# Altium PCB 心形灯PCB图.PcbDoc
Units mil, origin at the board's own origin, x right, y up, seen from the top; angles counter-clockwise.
Board outline 5315 x 3937.01 mil, 2 copper layers (Top Layer, Bottom Layer); 75 components, 69 nets, 202 pads, 0 vias.
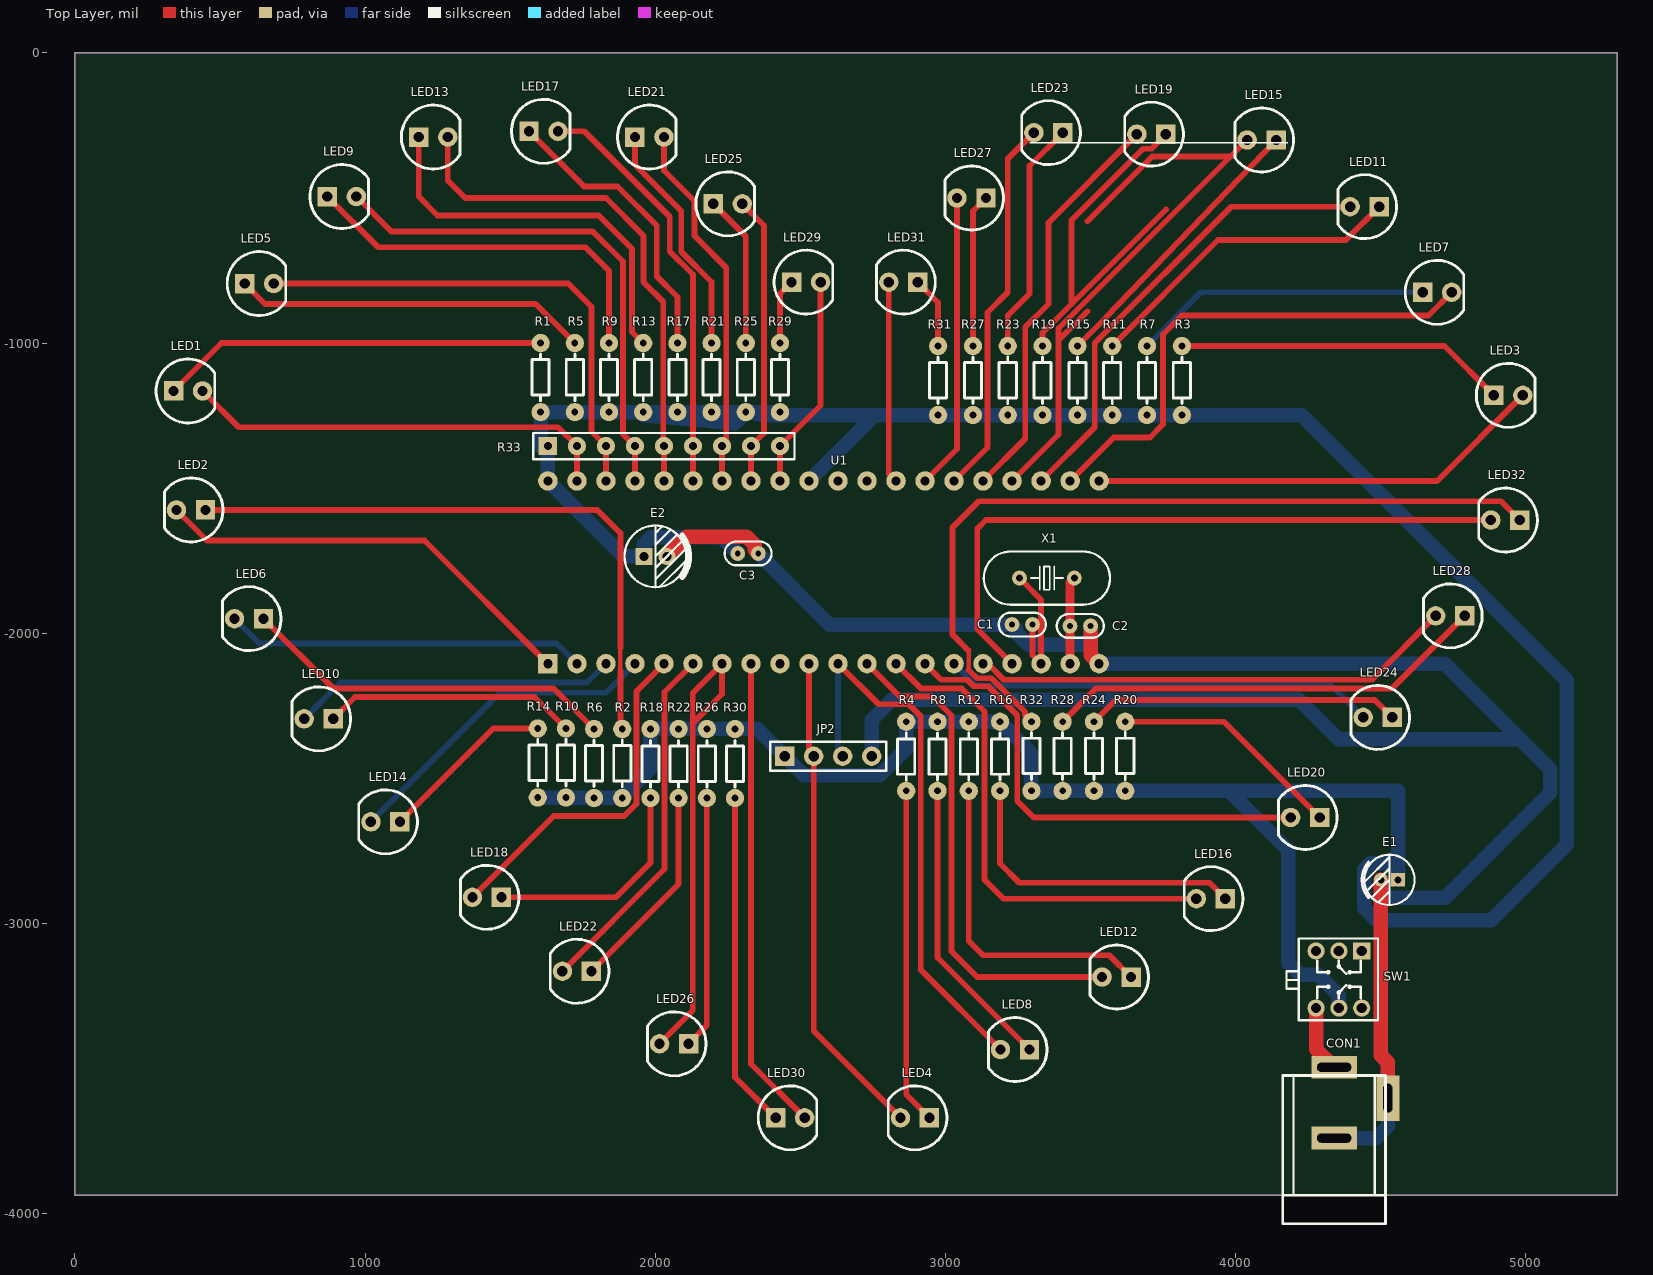
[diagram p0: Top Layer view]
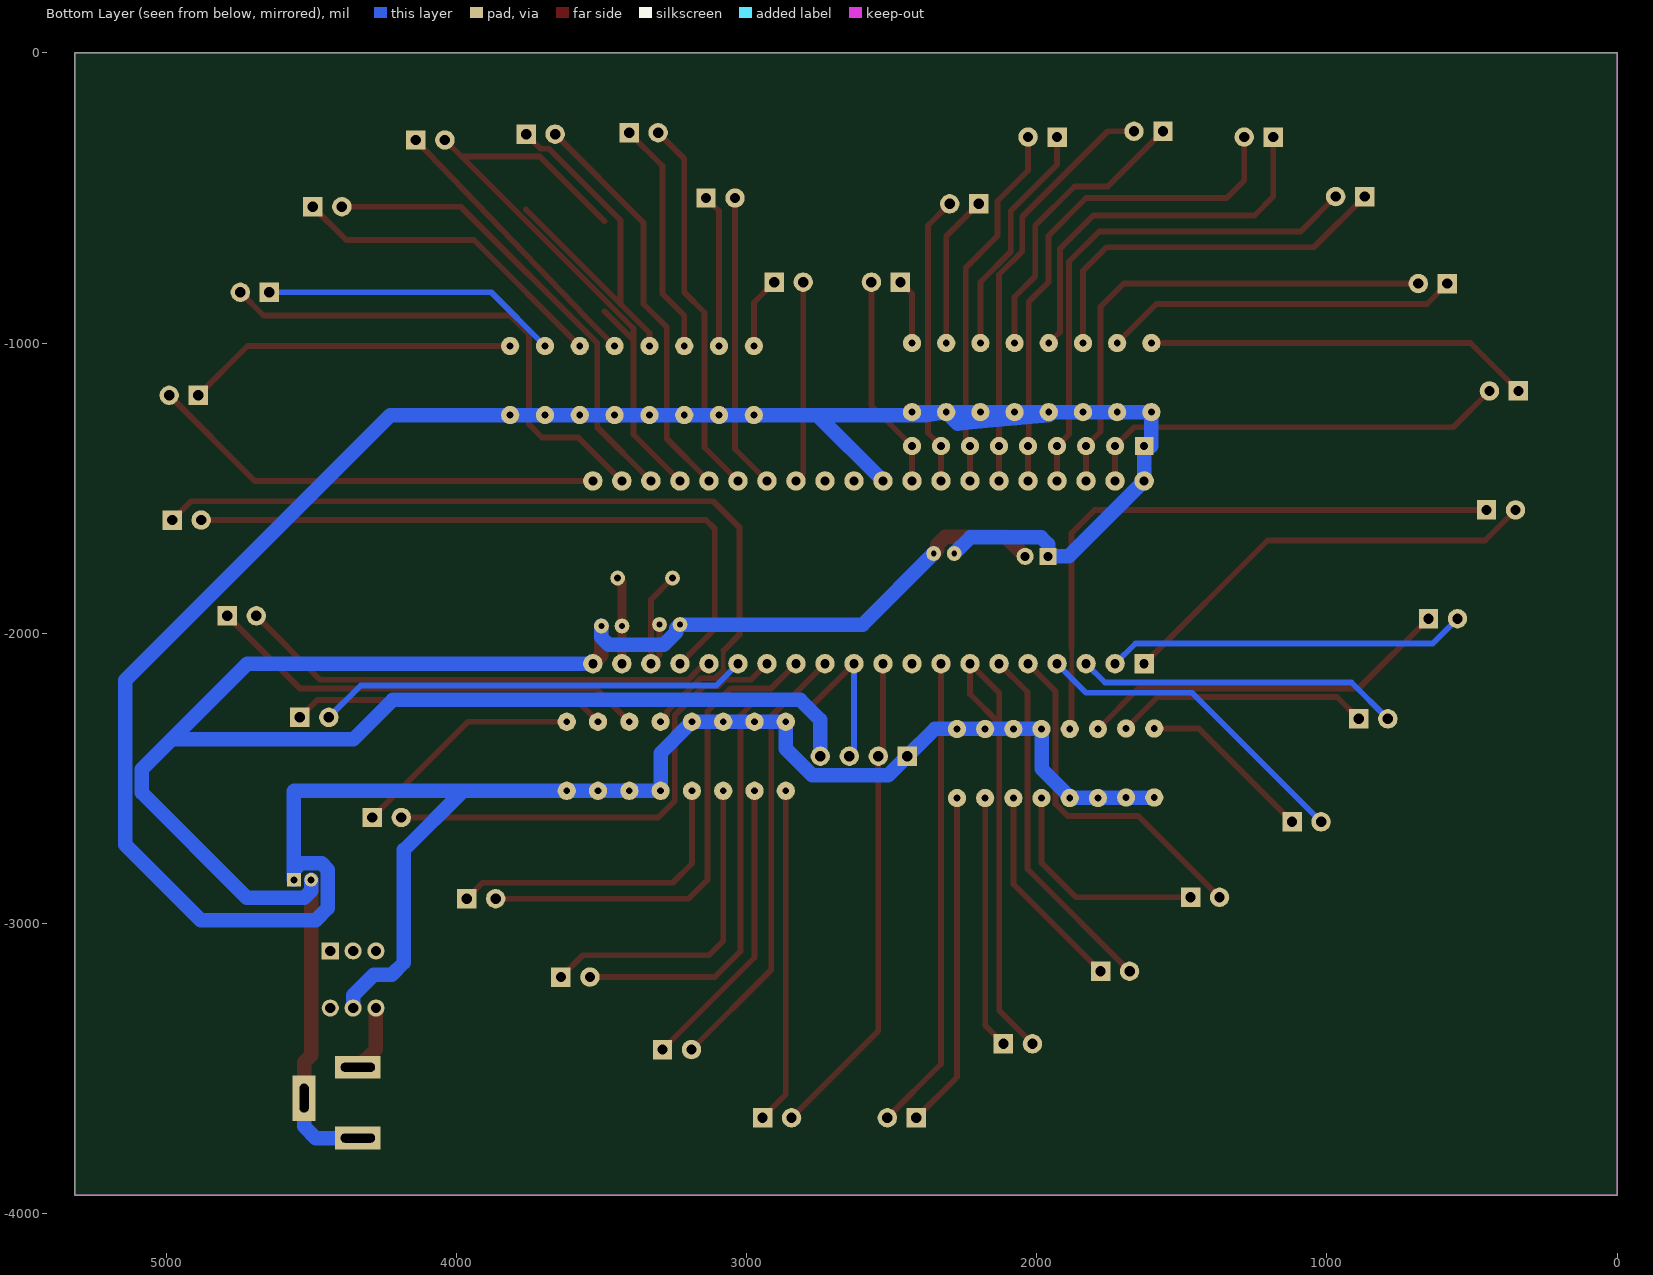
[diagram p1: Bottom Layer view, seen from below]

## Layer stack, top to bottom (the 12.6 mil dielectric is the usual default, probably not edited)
Top Solder: solder mask 0.4, Solder Resist, Dk 3.5
Top Layer: signal copper 1.4
Dielectric 1: dielectric 12.6, FR-4, Dk 4.8
Bottom Layer: signal copper 1.4
Bottom Solder: solder mask 0.4, Solder Resist, Dk 3.5

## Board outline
0,-3937.01 0,0 5315,0 5315,-3937.01

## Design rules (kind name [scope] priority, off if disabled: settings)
Clearance [All] p1: gap=7
PolygonConnect [All] p1: connectstyle=Relief reliefconductorwidth=10 reliefentries=4 polygonreliefangle="90 Angle" airgapwidth=10
RoutingVias [All] p1: holewidth=28 width=50 viastyle="Through Hole" minholewidth=28 minwidth=50 maxholewidth=28 maxwidth=50
SolderMaskExpansion [All] p1: expansion=4
Width Width-POWER [InNetClass('POWER')] p1: maxlimit=60 minlimit=50 preferedwidth=50
Width Width_1 [All] p2: maxlimit=30 minlimit=10 preferedwidth=20
30 further rules are at their usual default settings.

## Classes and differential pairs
net class POWER: +5V GND VCC

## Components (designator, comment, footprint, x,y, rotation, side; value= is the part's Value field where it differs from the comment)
C1 "104" "CC 1.8*3.6" 3265,-1970 r0 top
C2 "104" "CC 1.8*3.6" 3465,-1975 r180 top
C3 "104" "CC 1.8*3.6" 2320,-1725 r180 top
CON1 "3.5*1.3" DC-005 4340,-3740 r270 top
E1 "10uF/16V" "CAP 1.5*4*8" 4530.47,-2850 r180 top
E2 "100uF/16V" "CAP 2.0*5*11" 2000.63,-1735 r0 top
JP2 "TTL下载" HDR2.54-LI-4P 2596.06,-2423.94 r0 top
LED1 "红色" "LED 5MM-W" 390,-1165 r0 top
LED2 "红色" "LED 5MM-W" 400,-1575 r180 top
LED3 "红色" "LED 5MM-W" 4940,-1180 r0 top
LED4 "红色" "LED 5MM-W" 2895,-3670 r180 top
LED5 "红色" "LED 5MM-W" 635,-795 r0 top
LED6 "红色" "LED 5MM-W" 600,-1950 r180 top
LED7 "红色" "LED 5MM-W" 4695,-825 r0 top
LED8 "红色" "LED 5MM-W" 3240,-3435 r180 top
LED9 "红色" "LED 5MM-W" 920,-495 r0 top
LED10 "红色" "LED 5MM-W" 840,-2295 r180 top
LED11 "红色" "LED 5MM-W" 4445,-530 r180 top
LED12 "红色" "LED 5MM-W" 3590,-3185 r180 top
LED13 "红色" "LED 5MM-W" 1235,-290 r0 top
LED14 "红色" "LED 5MM-W" 1070,-2650 r180 top
LED15 "红色" "LED 5MM-W" 4090,-300 r180 top
LED16 "红色" "LED 5MM-W" 3915,-2915 r180 top
LED17 "红色" "LED 5MM-W" 1615,-270 r0 top
LED18 "红色" "LED 5MM-W" 1420,-2910 r180 top
LED19 "红色" "LED 5MM-W" 3710,-280 r180 top
LED20 "红色" "LED 5MM-W" 4240,-2635 r180 top
LED21 "红色" "LED 5MM-W" 1980,-290 r0 top
LED22 "红色" "LED 5MM-W" 1730,-3165 r180 top
LED23 "红色" "LED 5MM-W" 3355,-275 r180 top
LED24 "红色" "LED 5MM-W" 4490,-2290 r180 top
LED25 "红色" "LED 5MM-W" 2250,-520 r0 top
LED26 "红色" "LED 5MM-W" 2065,-3415 r180 top
LED27 "红色" "LED 5MM-W" 3090,-500 r180 top
LED28 "红色" "LED 5MM-W" 4740,-1940 r180 top
LED29 "红色" "LED 5MM-W" 2520,-790 r0 top
LED30 "红色" "LED 5MM-W" 2465,-3670 r0 top
LED31 "红色" "LED 5MM-W" 2855,-790 r180 top
LED32 "红色" "LED 5MM-W" 4930,-1610 r180 top
R1 "1K" "RS 1/8W" 1605,-1120 r270 top
R2 "1K" "RS 1/8W" 1886.43,-2450 r270 top
R3 "1K" "RS 1/8W" 3815,-1130 r270 top
R4 "1K" "RS 1/8W" 2865,-2423.11 r90 top
R5 "1K" "RS 1/8W" 1722.86,-1120 r270 top
R6 "1K" "RS 1/8W" 1789.29,-2450 r270 top
R7 "1K" "RS 1/8W" 3695,-1130 r270 top
R8 "1K" "RS 1/8W" 2972.86,-2423.11 r90 top
R9 "1K" "RS 1/8W" 1840.71,-1120 r270 top
R10 "1K" "RS 1/8W" 1692.14,-2448.11 r270 top
R11 "1K" "RS 1/8W" 3575,-1130 r270 top
R12 "1K" "RS 1/8W" 3080.71,-2423.11 r90 top
R13 "1K" "RS 1/8W" 1958.57,-1120 r270 top
R14 "1K" "RS 1/8W" 1595,-2448.11 r270 top
R15 "1K" "RS 1/8W" 3455,-1130 r270 top
R16 "1K" "RS 1/8W" 3188.57,-2423.11 r90 top
R17 "1K" "RS 1/8W" 2076.43,-1120 r270 top
R18 "1K" "RS 1/8W" 1983.57,-2448.11 r90 top
R19 "1K" "RS 1/8W" 3335,-1130 r270 top
R20 "1K" "RS 1/8W" 3620,-2425 r270 top
R21 "1K" "RS 1/8W" 2194.28,-1120 r270 top
R22 "1K" "RS 1/8W" 2080.71,-2448.11 r90 top
R23 "1K" "RS 1/8W" 3215,-1130 r270 top
R24 "1K" "RS 1/8W" 3512.14,-2425 r270 top
R25 "1K" "RS 1/8W" 2312.14,-1120 r270 top
R26 "1K" "RS 1/8W" 2177.86,-2448.11 r90 top
R27 "1K" "RS 1/8W" 3095,-1130 r270 top
R28 "1K" "RS 1/8W" 3404.29,-2425 r270 top
R29 "1K" "RS 1/8W" 2430,-1120 r270 top
R30 "1K" "RS 1/8W" 2275,-2448.11 r90 top
R31 "1K" "RS 1/8W" 2975,-1130 r270 top
R32 "1K" "RS 1/8W" 3296.43,-2425 r270 top
R33 "103" "R SIP9-2.54" 2030,-1355 r0 top
SW1 "KET 7X7" "KFT DIP-7X7" 4356.26,-3193.43 r180 top
U1 "STC89C52RC" 单片机40 1630,-2105 r90 top
X1 "12MHz" "OSC HC-49U" 3350,-1810 r180 top

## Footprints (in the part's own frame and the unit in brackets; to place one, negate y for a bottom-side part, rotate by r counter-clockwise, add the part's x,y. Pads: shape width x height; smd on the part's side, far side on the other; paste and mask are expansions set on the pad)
"CAP 1.5*4*8" [mm] "脚距1.5mm直径4mm高度8mm"
  rect 1.2x1.2 hole 0.6: 1(-0.75,0)
  round 1.2 hole 0.6: 2(0.75,0)
  silkscreen extent -2.2,-2.2 2.41,2.2, body extent -2,-2 2.02,2, height 8.04
"CAP 2.0*5*11" [mm] "脚距2mm直径5mm高度11mm"
  rect 1.5x1.5 hole 0.8: 1(-1,0)
  round 1.5 hole 0.8: 2(1,0)
  silkscreen extent -2.7,-2.7 2.96,2.7, body extent -2.5,-2.5 2.51,2.5, height 11.04
"CC 1.8*3.6" [mm] "脚距1.8mm直径3.6mm"
  round 1.3 hole 0.5: 1(-0.9,0) 2(0.9,0)
  silkscreen extent -2.05,-1.04 2.05,1.04, body extent -1.8,-0.8 1.8,0.8, height 3.6
DC-005 [mm] "5.5*2.1mm，DC30V,2.5A"
  rect 2x4 hole 0.8 slot 3 at 90 deg: 1(-6.2,0) 2(0,0)
  rect 4x2 hole 0.8 slot 2.5 at 0 deg: 3(-3.5,4.7)
  silkscreen extent -5.48,-4.5 7.5,4.5, body extent -6.55,-4.5 7.5,4.8, height 11.2
HDR2.54-LI-4P [mm] "排针，4脚"
  rect 1.7x1.7 hole 0.9: 1(-3.81,0)
  round 1.7 hole 0.9: 2(-1.27,0) 3(1.27,0) 4(3.81,0)
  silkscreen extent -5.08,-1.27 5.08,1.27, body extent -5.08,-1.27 5.08,1.27, height 8.5
"KFT DIP-7X7" [mm] "自锁开关，规格：7*7mm"
  rect 1.5x1.5 hole 0.9: 1(-2,-2.5)
  round 1.5 hole 0.9: 2(0,-2.5) 3(2,-2.5) 4(2,2.5) 5(0,2.5) 6(-2,2.5)
  silkscreen extent -3.42,-3.58 4.58,3.56, body extent -3.5,-3.5 3.5,3.5, height 11.2
"LED 5MM-W" [mm] "白色5mm直插LED"
  rect 1.7x1.7 hole 0.9: 1(-1.27,0)
  round 1.7 hole 0.9: 2(1.27,0)
  silkscreen extent -2.8,-2.8 2.33,2.8, body extent -2.85,-2.85 2.45,2.85, height 8.75
"OSC HC-49U" [mm]
  round 1.3 hole 0.6: 1(-2.4,0) 2(2.4,0)
  silkscreen extent -5.52,-2.32 5.52,2.33, body extent -5.53,-2.33 5.52,2.32, height 13.95
"R SIP9-2.54" [mm] "22.6mm*5mm*2.2mm(长*宽*厚)"
  rect 1.6x1.6 hole 0.7: 1(-10.16,0)
  round 1.6 hole 0.7: 2(-7.62,0) 3(-5.08,0) 4(-2.54,0) 5(0,0) 6(2.54,0) 7(5.08,0) 8(7.62,0) 9(10.16,0)
  silkscreen extent -11.43,-1.14 11.43,1.14, body extent -11.31,-0.96 11.31,0.96, height 5.2
"RS 1/8W" [mm] "直插色环电阻，脚距6mm，直径1.5mm"
  round 1.6 hole 0.6: 1(-3.048,0) 2(3,0)
  silkscreen extent -2.1,-0.75 2,0.75, body extent -3.22,-0.76 3.23,0.76, height 1.52
单片机40 [mm]
  rect 1.7x1.7 hole 0.8: 1(0,0)
  round 1.7 hole 0.8: 2(0,-2.54) 3(0,-5.08) 4(0,-7.62) 5(0,-10.16) 6(0,-12.7) 7(0,-15.24) 8(0,-17.78) 9(0,-20.32) 10(0,-22.86) 11(0,-25.4) 12(0,-27.94) 13(0,-30.48) 14(0,-33.02) 15(0,-35.56) 16(0,-38.1) 17(0,-40.64) 18(0,-43.18) 19(0,-45.72) 20(0,-48.26) 21(16,-48.26) 22(16,-45.72) 23(16,-43.18) 24(16,-40.64) 25(16,-38.1) 26(16,-35.56) 27(16,-33.02) 28(16,-30.48) 29(16,-27.94) 30(16,-25.4) 31(16,-22.86) 32(16,-20.32) 33(16,-17.78) 34(16,-15.24) 35(16,-12.7) 36(16,-10.16) 37(16,-7.62) 38(16,-5.08) 39(16,-2.54) 40(16,0)

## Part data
C1 C2 C3: library part C-CC, "直插瓷片电容"
CON1: library part P-DC, "低压电源接口"
E1 E2: library part C-CAP, "直插电解电容"
JP2: library part "Header 4", "4P接插件"
LED1 LED2 LED3 LED4 LED5 LED6 LED7 LED8 LED9 LED10 LED11 LED12 LED13 LED14 LED15 LED16 LED17 LED18 LED19 LED20 LED21 LED22 LED23 LED24 LED25 LED26 LED27 LED28 LED29 LED30 LED31 LED32: library part LED-5MM, "5mm插件LED"
R1 R2 R3 R4 R5 R6 R7 R8 R9 R10 R11 R12 R13 R14 R15 R16 R17 R18 R19 R20 R21 R22 R23 R24 R25 R26 R27 R28 R29 R30 R31 R32: library part R-CRR, "直插色环电阻"
R33: library part "R SIP9", "单列直插排阻"
SW1: "7*7自锁开关"
U1: "STC单片机"
X1: library part XTAL-2P, "2脚无源脚晶振"

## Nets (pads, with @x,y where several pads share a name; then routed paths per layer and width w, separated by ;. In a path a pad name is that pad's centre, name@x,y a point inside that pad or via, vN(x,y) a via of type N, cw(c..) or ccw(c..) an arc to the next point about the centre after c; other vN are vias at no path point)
+5V: CON1.1 SW1.4 | length 229.9
  Top Layer w50: SW1.4 4277.52,-3433.43 CON1.1
GND: C1.1 C2.1 C3.1 CON1.2 CON1.3 E1.2 E2.2 JP2.4 U1.20 | length 7926.3
  Top Layer w50: E2.2 2108,-1667 2315,-1667 2343,-1695 2343,-1712.57 C3.1 ; C2.1 3500.43,-2075.43 U1.20 ; E1.2 4500.94,-3453.94 4525.04,-3478.04 CON1.3
  Bottom Layer w50: C3.1 2600.43,-1970 C1.1 3242,-1982.43 3242,-1996.54 3285,-2039.54 3475.46,-2039.54 3500.43,-2014.57 C2.1 ; JP2.4 2746.06,-2298.94 2815,-2230 4220,-2230 4355,-2365 4981,-2365 ; U1.20 4721,-2105 4981,-2365 ; CON1.2 4485,-3740 4525.04,-3699.96 CON1.3 ; E1.2 4500.94,-2886.94 4525,-2911 4723,-2911 5085,-2549 5085,-2469 4981,-2365
NetC1_2: C1.2 U1.18 X1.2 | length 473.1
  Top Layer w20: X1.2 3330,-1884.49 U1.18 3300.43,-2075.43 C1.2
NetC2_2: C2.2 U1.19 X1.1 | length 301.4
  Top Layer w30: U1.19 3429.57,-2104.57 C2.2 3429.57,-1824.92 X1.1
NetLED1_1: LED1.1 R1.1 | length 1333.3
  Top Layer w20: LED1.1 505,-1000 R1.1
NetLED2_1: LED2.1 R2.1 | length 2140.8
  Top Layer w15: 1880,-2130 1880,-2050
  Top Layer w20: LED2.1 1800,-1575 1880,-1655 1880,-2050 ; 1880,-2130 1880,-2323.57 R2.1
NetLED3_1: LED3.1 R3.1 | length 1145.4
  Top Layer w20: R3.1 4720,-1010 LED3.1
NetLED4_1: LED4.1 R4.1 | length 1160
  Top Layer w20: R4.1 2865,-3590 LED4.1
NetLED5_1: LED5.1 R5.1 | length 1222.8
  Top Layer w20: LED5.1 655,-865 1587.86,-865 R5.1
NetLED6_1: LED6.1 R6.1 | length 1296.7
  Top Layer w20: LED6.1 890,-2190 1649.29,-2190 R6.1
NetLED7_1: LED7.1 R7.1 | length 1026.6
  Bottom Layer w20: R7.1 3880,-825 LED7.1
NetLED8_1: LED8.1 R8.1 | length 1023.3
  Top Layer w20: R8.1 2972.86,-3117.86 LED8.1
NetLED9_1: LED9.1 R9.1 | length 1325.9
  Top Layer w20: LED9.1 1045,-670 1760,-670 1840.71,-750.71 R9.1
NetLED10_1: LED10.1 R10.1 | length 878
  Top Layer w20: LED10.1 965,-2220 1584.03,-2220 R10.1
NetLED11_1: LED11.1 R11.1 | length 1118.8
  Top Layer w20: R11.1 3940,-645 4380,-645 LED11.1
NetLED12_1: LED12.1 R12.1 | length 1128.4
  Top Layer w20: R12.1 3080.71,-3060.71 3130,-3110 3565,-3110 LED12.1
NetLED13_1: LED13.1 R13.1 | length 1355.5
  Top Layer w20: LED13.1 1185,-495 1250,-560 1805,-560 1920,-675 1920,-961.43 R13.1
NetLED14_1: LED14.1 R14.1 | length 608.3
  Top Layer w20: LED14.1 1441.89,-2328.11 R14.1
NetLED15_1: LED15.1 R15.1 | length 986.6
  Top Layer w20: R15.1 3555,-910 LED15.1
NetLED16_1: LED16.1 R16.1 | length 1077.2
  Top Layer w20: R16.1 3188.57,-2793.57 3255,-2860 3910,-2860 LED16.1
NetLED17_1: LED17.1 R17.1 | length 1009.2
  Top Layer w20: LED17.1 1755,-460 1870,-460 2005,-595 2005,-770 2076.43,-841.43 R17.1
NetLED18_1: LED18.1 R18.1 | length 786
  Top Layer w20: LED18.1 1865,-2910 1983.57,-2791.43 R18.1
NetLED19_1: LED19.1 R19.1 | length 1382.4
  Top Layer w20: R19.1 3335,-965 3435,-865 ; 3760,-540 3435,-865 ; LED19.1 3710,-330 3681.37,-330 3435,-576.37 3435,-865
NetLED20_1: LED20.1 R20.1 | length 806.7
  Top Layer w20: R20.1 3960,-2305 LED20.1
NetLED21_1: LED21.1 R21.1 | length 819.5
  Top Layer w20: LED21.1 1930,-385 2090,-545 2090,-685 2194.29,-789.28 R21.1
NetLED22_1: LED22.1 R22.1 | length 721.4
  Top Layer w20: LED22.1 2080.71,-2864.29 R22.1
NetLED23_1: LED23.1 R23.1 | length 813.7
  Top Layer w20: R23.1 3215,-905 3290,-830 3290,-390 LED23.1
NetLED24_1: LED24.1 R24.1 | length 1083.8
  Top Layer w20: R24.1 3587.14,-2230 4480,-2230 LED24.1
NetLED25_1: LED25.1 R25.1 | length 526.5
  Top Layer w20: LED25.1 2312.14,-632.14 R25.1
NetLED26_1: LED26.1 R26.1 | length 872.9
  Top Layer w20: LED26.1 2177.86,-3352.14 R26.1
NetLED27_1: LED27.1 R27.1 | length 528.6
  Top Layer w20: R27.1 3095,-545 LED27.1
NetLED28_1: LED28.1 R28.1 | length 1536.9
  Top Layer w20: R28.1 3519.29,-2190 4540,-2190 LED28.1
NetLED29_1: LED29.1 R29.1 | length 226.6
  Top Layer w20: R29.1 2430,-830 LED29.1
NetLED30_1: LED30.1 R30.1 | length 1159.9
  Top Layer w20: R30.1 2275,-3530 LED30.1
NetLED31_1: LED31.1 R31.1 | length 249
  Top Layer w20: LED31.1 2975,-860 R31.1
NetLED32_1: LED32.1 R32.1 | length 2830.7
  Top Layer w15: 3080,-2126.37 3080,-2060
  Top Layer w20: 3080,-2126.37 3109.1,-2155.46 3158.65,-2155.46 3274.93,-2271.75 3274.93,-2283.5 R32.1 ; 3080,-2060 3025,-2005 3025,-1635 3115,-1545 4915,-1545 LED32.1
P0_0: LED1.2 R33.2 U1.39 | length 1488.8
  Top Layer w20: LED1.2 565,-1290 1665,-1290 R33.2 U1.39
P0_1: LED5.2 R33.3 U1.38 | length 1748.9
  Top Layer w20: LED5.2 1700,-795 1780,-875 1780,-1305 R33.3 U1.38
P0_2: LED9.2 R33.4 U1.37 | length 1784.8
  Top Layer w20: LED9.2 1090,-615 1785,-615 1889.21,-719.21 1889.21,-1314.21 R33.4 U1.37
P0_3: LED13.2 R33.5 U1.36 | length 1777.8
  Top Layer w20: LED13.2 1285,-440 1345,-500 1830,-500 1960,-630 1960,-790 2027.93,-857.93 2027.93,-1352.93 R33.5 U1.36
P0_4: LED17.2 R33.6 U1.35 | length 1450.4
  Top Layer w20: LED17.2 1755,-270 2050,-565 2050,-684 2130,-764 R33.6 U1.35
P0_5: LED21.2 R33.7 U1.34 | length 1280.3
  Top Layer w20: LED21.2 2030,-405 2135,-510 2135,-630 2245,-740 2245,-1340 R33.7 U1.34
P0_6: LED25.2 R33.8 U1.33 | length 1004.8
  Top Layer w20: LED25.2 2375,-595 2375,-1310 R33.8 U1.33
P0_7: LED29.2 R33.9 U1.32 | length 743.1
  Top Layer w20: U1.32 R33.9 2570,-1215 LED29.2
P1_0: LED2.2 U1.1 | length 1499.5
  Top Layer w20: LED2.2 455,-1680 1205,-1680 U1.1
P1_1: LED6.2 U1.2 | length 1244.2
  Bottom Layer w20: LED6.2 635,-2035 1660,-2035 U1.2
P1_2: LED10.2 U1.3 | length 1118.7
  Bottom Layer w20: LED10.2 915,-2170 1765,-2170 U1.3
P1_3: LED14.2 U1.4 | length 1135.7
  Bottom Layer w20: LED14.2 1465,-2205 1830,-2205 U1.4
P1_4: LED18.2 U1.5 | length 1220.8
  Top Layer w20: LED18.2 1650,-2630 1893.12,-2630 1935.07,-2588.05 1935.07,-2199.93 U1.5
P1_5: LED22.2 U1.6 | length 1246.4
  Top Layer w20: LED22.2 2032.22,-2812.78 2032.22,-2202.78 U1.6
P1_6: LED26.2 U1.7 | length 1645.7
  Top Layer w20: LED26.2 2129.36,-3300.64 2129.36,-2309.91 ; 2129.36,-2309.91 2129.36,-2205.64 U1.7 2230,-2209.27 2129.36,-2309.91
P1_7: LED30.2 U1.8 | length 1641.6
  Top Layer w20: U1.8 2330,-3485 LED30.2
P2_0: LED3.2 U1.21 | length 1582.2
  Top Layer w20: U1.21 4694.92,-1475.08 LED3.2
P2_1: LED7.2 U1.22 | length 1765.9
  Top Layer w20: U1.22 3580.08,-1325 3705,-1325 3750,-1280 3750,-970 3815,-905 4665,-905 LED7.2
P2_2: LED11.2 U1.23 | length 1626.4
  Top Layer w20: U1.23 3515,-1290.08 3515,-1000 3985,-530 LED11.2
P2_3: LED15.2 U1.24 | length 2237.4
  Top Layer w20: U1.24 3390,-1315.08 3390,-990 ; 3490,-890 3390,-990 ; 3490,-580 3713,-357 3983,-357 ; LED15.2 3983,-357 ; 3390,-990 3390,-950 3983,-357
P2_4: LED19.2 U1.25 | length 1414.6
  Top Layer w20: U1.25 3275,-1330.08 3275,-945 3355,-865 3355,-585 LED19.2
P2_5: LED23.2 U1.26 | length 1314
  Top Layer w20: U1.26 3145,-1360.08 3145,-895 3215,-825 3215,-365 LED23.2
P2_6: LED27.2 U1.27 | length 1020.6
  Top Layer w20: U1.27 3040,-1365.08 LED27.2
P2_7: LED31.2 U1.28 | length 695.4
  Top Layer w20: LED31.2 2805,-1450.08 U1.28
P3_0: JP2.2 LED4.2 U1.10 | length 1695.5
  Top Layer w20: U1.10 2530,-2407.87 JP2.2 2546.06,-3371.06 LED4.2
P3_1: JP2.3 LED8.2 U1.11 | length 1948.2
  Top Layer w20: U1.11 2770,-2245 2873.58,-2245 2915,-2286.42 2915,-3160 LED8.2
  Bottom Layer w20: U1.11 2630,-2407.87 JP2.3
P3_2: LED12.2 U1.12 | length 1733.5
  Top Layer w20: U1.12 2843,-2218 2955.79,-2218 3021.35,-2283.56 3021.35,-3096.35 3110,-3185 LED12.2
P3_3: LED16.2 U1.13 | length 1710.3
  Top Layer w20: U1.13 2915,-2190 3055,-2190 3135,-2270 3135,-2850 3200,-2915 LED16.2
P3_4: LED20.2 U1.14 | length 1652.3
  Top Layer w20: U1.14 2985,-2160 3075.45,-2160 3097.91,-2182.46 3147.46,-2182.46 3247.93,-2282.93 3247.93,-2577.93 3305,-2635 LED20.2
P3_5: LED24.2 U1.15 | length 1486.6
  Bottom Layer w20: U1.15 3105,-2180 4330,-2180 LED24.2
P3_6: LED28.2 U1.16 | length 1673.9
  Top Layer w20: U1.16 3131,-2106 3147.37,-2106 3201.37,-2160 4470,-2160 LED28.2
P3_7: LED32.2 U1.17 | length 2297.1
  Top Layer w20: U1.17 3110,-1985 3110,-1640 3140,-1610 LED32.2
VCC: C3.2 E1.1 E2.1 JP2.1 R1.2 R2.2 R3.2 R4.2 R5.2 R6.2 R7.2 R8.2 R9.2 R10.2 R11.2 R12.2 R13.2 R14.2 R15.2 R16.2 R17.2 R18.2 R19.2 R20.2 R21.2 R22.2 R23.2 R24.2 R25.2 R26.2 R27.2 R28.2 R29.2 R30.2 R31.2 R32.2 R33.1 SW1.5 U1.31 U1.40 | length 12261.3
  Bottom Layer w50: R14.2 R10.2 R6.2@1789.29,-2566.22 ; R6.2 R6.2@1789.29,-2566.22 ; R2.2 R2.2@1884.54,-2566.22 ; C3.2 2229.57,-1670 1985,-1670 1961.26,-1693.74 E2.1 1889.92,-1735 U1.40 R33.1 1605,-1355 R1.2 R5.2 R9.2 R13.2 ; R29.2 R25.2 ; U1.31 2756.97,-1248.11 ; SW1.5 4356.26,-3248.26 4285,-3177 4223,-3177 4181,-3135 4181,-2747 3977.11,-2543.11 ; E1.1 4560,-2817 ; R6.2@1789.29,-2566.22 R2.2@1884.54,-2566.22 ; R2.2@1884.54,-2566.22 1983.57,-2467.19 R18.2 R22.2 R26.2 R30.2 2352.13,-2330 JP2.1 2511.53,-2489.4 2773.18,-2489.4 2865,-2397.58 R4.2 R8.2 R12.2 R16.2 3296.43,-2412.86 R32.2 R28.2 R24.2 R20.2 3977.11,-2543.11 ; R13.2 R17.2 R21.2 R25.2 ; R13.2 1958.57,-1248.11 2074.49,-1258.91 2191.33,-1269.8 2272.86,-1277.4 R25.2 ; R25.2 2381.86,-1248.11 2756.97,-1248.11 ; 2756.97,-1248.11 R31.2 R27.2 R23.2 R19.2 R15.2 R11.2 R7.2 R3.2 4228.11,-1248.11 5142,-2162 5142,-2729 4882,-2989 4485,-2989 4443,-2947 4443,-2815 4465,-2793 4536,-2793 4560,-2817 ; 3977.11,-2543.11 4559.11,-2543.11 4560,-2544 4560,-2817
pads on no net: SW1.1 SW1.2 SW1.3 SW1.6 U1.9 U1.29 U1.30

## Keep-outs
Keep-Out Layer:
  the board outline again, w5

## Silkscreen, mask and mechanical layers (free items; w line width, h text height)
Top Overlay:
  lines w5: 3290,-310 4180,-310

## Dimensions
0,0 to 5315,0 on Keep-Out Layer
0,0 to 0,-3937.01 on Keep-Out Layer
